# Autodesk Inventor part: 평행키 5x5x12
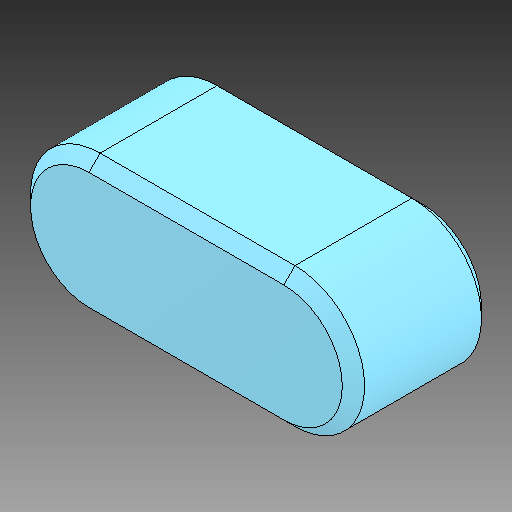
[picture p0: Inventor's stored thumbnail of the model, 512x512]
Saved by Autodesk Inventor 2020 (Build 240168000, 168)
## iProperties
Created: 2024-08
Part Number: 평행키 5x5x12
Material: 강철, 연강
Description: 키 및 해당 키홈
Document SubType Name: Modeling
Designer: 1강의실14
Density: 7.85 g/cm^3
Appearance: 기본값
Author: jhkim
Sending System: Autodesk Inventor 2025
Preprocessor: ST-DEVELOPER v20
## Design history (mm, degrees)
feature "Solid1"
node "솔리드1"
